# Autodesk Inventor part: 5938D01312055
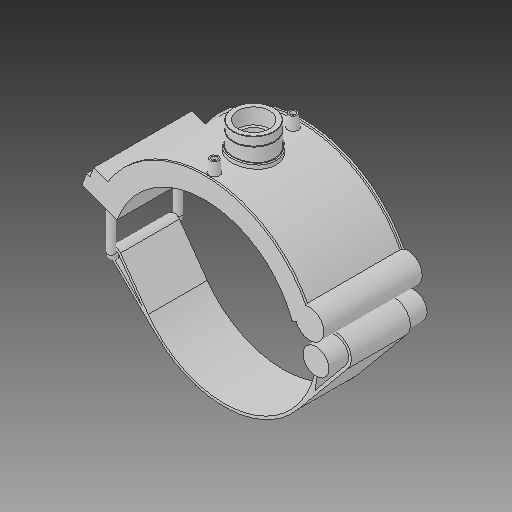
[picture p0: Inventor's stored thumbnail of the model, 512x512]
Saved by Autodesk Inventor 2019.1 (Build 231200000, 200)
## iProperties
Created: 2017-07
Part Number: 5938D01312055
Material: Generic
Description: PLASSON TRANSITION SADDLE 12''DIPS x 2"NPT
Document SubType Name: Modeling
Designer: KIM
Density: 1 g/cm^3
Appearance: Default
Author: KIM
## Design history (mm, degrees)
derived "5938D.ipt"
feature "Solid1::5938D.ipt"
tag "TaggingFeature1"
body "Solid1"
other parameters: "d0" = 333.8, "d1" = 400.56, "d2" = 487.045, "d3" = 83.45, "d4" = 176.022, "d5" = 0, "d40" = 208.2912, "d41" = 79.3184, "d43" = 0, "d45" = 0, "d47" = 247.016, "d48" = 73.6528, "d50" = 0, "d78" = 222.28, "d79" = 15, "d80" = 70.4088, "d82" = 5 deg, "d84" = 4, "d85" = 14, "d86" = 0, "d87" = 3, "d88" = 0, "d96" = 408.5712, "d97" = 3.52044, "d98" = 0, "d102" = 1.69968, "d103" = 56.656, "d104" = 28.0416, "d105" = 0, "d106" = 45.3248, "d108" = 0, "d109" = -15.57867, "d111" = 0.5, "d112" = 0.5, "d113" = 0, "d114" = 0.5, "d117" = 0.56656, "d120" = 140 deg, "d121" = 24.228, "d122" = 20 deg, "d123" = 1602.24, "d124" = 240.336, "d126" = 0, "d143" = 343.814, "d145" = 51.35385, "d149" = 5.007, "d150" = 56.48923, "d153" = 176.022, "d154" = 0, "d156" = 200.28, "d157" = 160 deg, "d159" = 13.352, "d161" = 5.007, "d162" = 105.6132, "d163" = 0, "d164" = 166.9, "d167" = 33.38, "d168" = 195.39512, "d170" = 5.007, "d172" = 0, "d173" = 1, "d175" = 166.9, "d176" = 20 deg, "d177" = 23.366, "d178" = 66.76, "d180" = 0, "d183" = 26.704, "d184" = 18.6928, "d185" = 57.20715, "d186" = 57.20715, "d187" = 200.28, "d188" = 20.028, "d189" = 23.366, "d190" = 0, "d191" = 240.336, "d193" = 13.352, "d194" = 6.8429, "d195" = 90 deg, "d197" = 0, "d199" = 0, "d_" = 333.8, "B_" = 194.818, "H_" = 46.736, "L_" = 176.022, "d_t" = 6, "G_" = 56.656, "d148" = 5.007, "d160" = 5.007, "d169" = 5.007, "d192" = 13.352
